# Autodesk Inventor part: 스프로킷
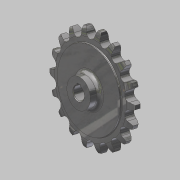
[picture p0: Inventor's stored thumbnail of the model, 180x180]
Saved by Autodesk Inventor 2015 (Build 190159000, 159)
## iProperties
Created: 2016-03
Part Number: 스프로킷
Material: 강철, 탄소
Document SubType Name: Modeling
Designer: mduedu
Density: 7.87 g/cm^3
Appearance: 반광택
Author: mduedu
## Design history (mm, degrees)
sketch "스케치1"
  geometry: L1 (0, 5)-(29.5, 5); L2 (29.5, 5)-(29.5, 4.1); L3 (30, 3.6)-(33.625, 3.6); L4 (40, 2)-(40, 0); L5 (40, 0)-(0, 0); L6 (0, 0)-(0, 5); L7 (0, -5)-(29.5, -5); L8 (29.5, -5)-(29.5, -4.1); L9 (30, -3.6)-(33.625, -3.6); L10 (40, -2)-(40, 0); L11 (0, 0)-(0, -5); A1 r 13.5 centre (33.625, -9.9) between (40, 2) and (33.625, 3.6); A2 r 13.5 centre (33.625, 9.9) between (33.625, -3.6) and (40, -2); A3 r 0.5 centre (30, 4.1) between (29.5, 4.1) and (30, 3.6); A4 r 0.5 centre (30, -4.1) between (30, -3.6) and (29.5, -4.1); 2 further points
  constraints: 22 end point, 8 point on circle, 6 symmetric about line, 5 tangent, 4 centre point, 4 parallel, 4 point on line, 1 equal radius, 1 horizontal, 1 perpendicular, 1 other
  dimensions: "d0" = 80 diameter of L4 L6; "d2" = 59 diameter of L2 L6; "d3" = 1.6 vertical distance of L4.start L3.end; "d4" = 3.6 distance from line of L4.end L3; "d5" = 5 distance between parallel lines of L5 L1; "d6" = 13.5 radius of A1; "d15" = 0.5 radius of A3
revolve "회전1" sketch "스케치1" stored, may be unused: angle "d7" = 90 deg
sketch "스케치2" dims "d8" = 65.2, "d11" = 80
  geometry: L1 (0, 0)-(0, 32.6); A1 r 36.57 centre (0, 0) between (-16.231, 32.771) and (0, 36.57); A2 r 3.97 centre (0, 36.57) between (-3.866, 35.665) and (0, 32.6); A3 r 12.7 centre (-16.231, 32.771) between (-3.866, 35.665) and (-5.534, 39.615); A4 r 12.7 centre (16.231, 32.771) between (5.534, 39.615) and (3.866, 35.665); A5 r 3.97 centre (0, 36.57) between (0, 32.6) and (3.866, 35.665); A6 r 40 centre (0, 0) between (5.534, 39.615) and (-5.534, 39.615); 2 further points
  constraints: 12 point on circle, 6 centre point, 4 coincident, 3 symmetric about line, 2 end point, 1 point on line, 1 tangent, 1 vertical, 1 vertical alignment, 7 other
  dimensions: "d10" = 73.14 diameter of A1; "d12" = 12.7 radius of A3
extrude "돌출1" cut sketch "스케치2" stored distance "d13" = 10; taper "d14" = 0 deg
sketch "스케치3"
  geometry: C1 r 11 at (0, 0); 1 further point
  constraints: 1 centre point, 1 coincident
  dimensions: "d19" = 22 diameter of C1
extrude "돌출2" join sketch "스케치3" distance "d20" = 8; taper "d21" = 0 deg
fillet "모깎기1" dims "d22" = 3
sketch "스케치4"
  geometry: L1 (-1.5, 0)-(1.5, 0); L2 (1.5, 0)-(1.5, 6.4); L3 (1.5, 6.4)-(-1.5, 6.4); L4 (-1.5, 6.4)-(-1.5, 0); C1 r 5 at (0, 0); 2 further points
  constraints: 8 end point, 2 coincident, 2 parallel, 1 centre point, 1 horizontal, 1 midpoint, 1 perpendicular
  dimensions: "d23" = 10 diameter of C1; "d25" = 3 distance of L2.end L3.end; "d26" = 6.4 distance of L1.end L2.end
extrude "돌출3" cut sketch "스케치4" stored distance "d27" = 8; taper "d28" = 0 deg
chamfer "모따기1" distance "d29" = 0.5; stored, may be unused: second distance "d30" = 2, angle "d31" = 45 deg
node "솔리드1"
pattern_circular "원형 패턴1" dims angle "d17" = 360 deg
